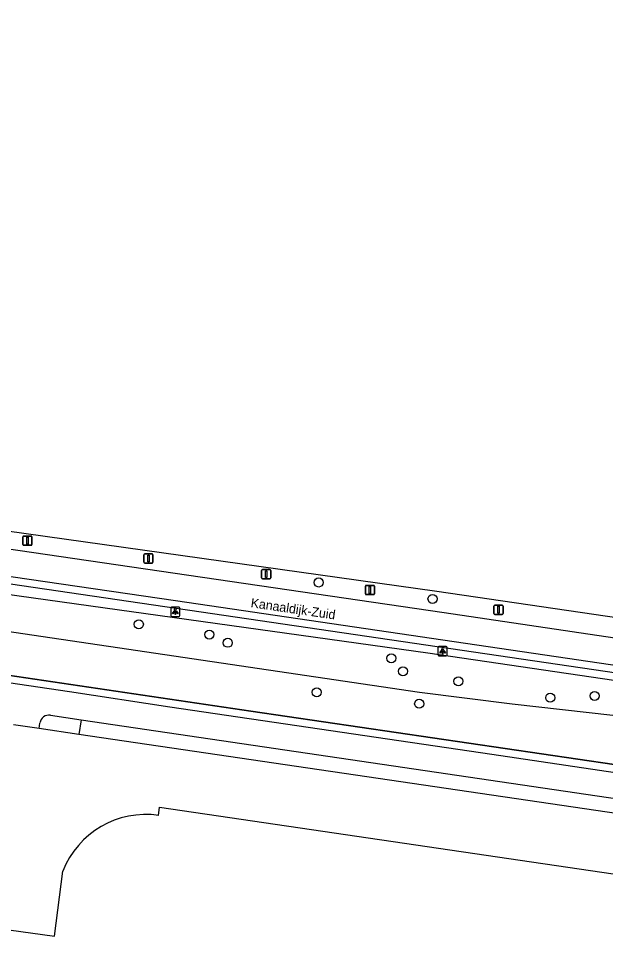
# Model space of a CAD drawing. Extents: x 163046 to 165074, y 382019 to 382874.
# Drawn here: x 163848.3 to 163911.6, y 382698.9 to 382799.6 of the extents above; entities that cross this region are included whole.
import ezdxf

# ---------------------------------------------------------------- set-up
doc = ezdxf.new("R2010")
doc.units = 0
for name, color, linetype in [('IMGEO_Afsluitpaal', 7, 'Continuous'), ('IMGEO_Boom', 7, 'Continuous'), ('IMGEO_Fietspad_gesloten', 7, 'Continuous'), ('IMGEO_Groenvoorziening', 7, 'Continuous'), ('IMGEO_Hek', 7, 'Continuous'), ('IMGEO_Lichtpunt', 7, 'Continuous'), ('IMGEO_Openbare_ruimte_label', 7, 'Continuous'), ('IMGEO_Rijbaan_lokaal_gesloten', 7, 'Continuous'), ('IMGEO_Rijbaan_lokaal_halfverhard', 7, 'Continuous'), ('IMGEO_Voetpad_open', 7, 'Continuous'), ('IMGEO_Waterloop', 7, 'Continuous')]:
    doc.layers.add(name, color=color, linetype=linetype)

msp = doc.modelspace()

# ---------------------------------------------------------------- linework, layer by layer
at = {"layer": 'IMGEO_Afsluitpaal'}
for p, q in [((163848.73, 382742.84), (163848.73, 382743.64)), ((163848.73, 382743.64), (163848.73, 382742.84)), ((163848.83, 382743.74), (163849.61, 382743.74)), ((163849.61, 382743.74), (163848.83, 382743.74)), ((163849.71, 382743.64), (163849.71, 382742.84)), ((163849.71, 382742.84), (163849.71, 382743.64)), ((163849.61, 382742.74), (163848.83, 382742.74)), ((163848.83, 382742.74), (163849.61, 382742.74)), ((163861.9, 382741.82), (163862.68, 382741.82)), ((163862.68, 382741.82), (163861.9, 382741.82)), ((163861.8, 382740.92), (163861.8, 382741.72)), ((163861.8, 382741.72), (163861.8, 382740.92)), ((163862.68, 382740.82), (163861.9, 382740.82)), ((163861.9, 382740.82), (163862.68, 382740.82)), ((163862.78, 382741.72), (163862.78, 382740.92)), ((163862.78, 382740.92), (163862.78, 382741.72)), ((163874.5, 382739.22), (163874.5, 382740.02)), ((163874.5, 382740.02), (163874.5, 382739.22)), ((163874.6, 382740.12), (163875.39, 382740.12)), ((163875.39, 382740.12), (163874.6, 382740.12)), ((163875.49, 382740.02), (163875.49, 382739.22)), ((163875.49, 382739.22), (163875.49, 382740.02)), ((163875.39, 382739.12), (163874.6, 382739.12)), ((163874.6, 382739.12), (163875.39, 382739.12)), ((163885.72, 382737.52), (163885.72, 382738.32)), ((163885.72, 382738.32), (163885.72, 382737.52)), ((163885.82, 382738.42), (163886.61, 382738.42)), ((163886.61, 382738.42), (163885.82, 382738.42)), ((163886.71, 382738.32), (163886.71, 382737.52)), ((163886.71, 382737.52), (163886.71, 382738.32)), ((163886.61, 382737.42), (163885.82, 382737.42)), ((163885.82, 382737.42), (163886.61, 382737.42)), ((163899.6, 382735.38), (163899.6, 382736.18)), ((163899.6, 382736.18), (163899.6, 382735.38)), ((163899.7, 382736.28), (163900.49, 382736.28)), ((163900.49, 382736.28), (163899.7, 382736.28)), ((163900.59, 382736.18), (163900.59, 382735.38)), ((163900.59, 382735.38), (163900.59, 382736.18)), ((163900.49, 382735.28), (163899.7, 382735.28)), ((163899.7, 382735.28), (163900.49, 382735.28))]:
    msp.add_line(p, q, dxfattribs=at)
for points in [[(163849.14, 382743.61), (163849.3, 382743.61), (163849.3, 382742.86), (163849.14, 382742.86), (163849.14, 382743.61)], [(163862.21, 382741.69), (163862.37, 382741.69), (163862.37, 382740.94), (163862.21, 382740.94), (163862.21, 382741.69)], [(163874.92, 382740), (163875.07, 382740), (163875.07, 382739.25), (163874.92, 382739.25), (163874.92, 382740)], [(163886.14, 382738.3), (163886.29, 382738.3), (163886.29, 382737.55), (163886.14, 382737.55), (163886.14, 382738.3)], [(163900.02, 382736.16), (163900.17, 382736.16), (163900.17, 382735.41), (163900.02, 382735.41), (163900.02, 382736.16)]]:
    msp.add_lwpolyline(points, dxfattribs=at)
for centre, start, end in [((163848.83, 382743.64), 90, 180), ((163848.83, 382743.64), 90, 180), ((163848.83, 382742.84), 180, 270), ((163848.83, 382742.84), 180, 270), ((163849.61, 382743.64), 0, 90), ((163849.61, 382743.64), 360, 90), ((163849.61, 382742.84), 270, 0), ((163849.61, 382742.84), 270, 0), ((163861.9, 382741.72), 90, 180), ((163861.9, 382741.72), 90, 180), ((163862.68, 382741.72), 0, 90), ((163862.68, 382741.72), 360, 90), ((163861.9, 382740.92), 180, 270), ((163861.9, 382740.92), 180, 270), ((163862.68, 382740.92), 270, 0), ((163862.68, 382740.92), 270, 0), ((163874.6, 382740.02), 90, 180), ((163874.6, 382740.02), 90, 180), ((163875.39, 382740.02), 0, 90), ((163875.39, 382740.02), 360, 90), ((163874.6, 382739.22), 180, 270), ((163874.6, 382739.22), 180, 270), ((163875.39, 382739.22), 270, 0), ((163875.39, 382739.22), 270, 0), ((163885.82, 382738.32), 90, 180), ((163885.82, 382738.32), 90, 180), ((163886.61, 382738.32), 0, 90), ((163886.61, 382738.32), 360, 90), ((163885.82, 382737.52), 180, 270), ((163885.82, 382737.52), 180, 270), ((163886.61, 382737.52), 270, 0), ((163886.61, 382737.52), 270, 0), ((163899.7, 382736.18), 90, 180), ((163899.7, 382736.18), 90, 180), ((163900.49, 382736.18), 0, 90), ((163900.49, 382736.18), 360, 90), ((163899.7, 382735.38), 180, 270), ((163899.7, 382735.38), 180, 270), ((163900.49, 382735.38), 270, 0), ((163900.49, 382735.38), 270, 0)]:
    msp.add_arc(centre, 0.1, start, end, dxfattribs=at)
at = {"layer": 'IMGEO_Boom'}
for centre in [(163880.68, 382738.73), (163892.97, 382736.96), (163861.25, 382734.22), (163868.87, 382733.11), (163870.86, 382732.22), (163888.52, 382730.55), (163889.78, 382729.15), (163895.77, 382728.07), (163880.47, 382726.88), (163905.68, 382726.29), (163910.47, 382726.49), (163891.53, 382725.64)]:
    msp.add_circle(centre, 0.489, dxfattribs=at)
at = {"layer": 'IMGEO_Fietspad_gesloten'}
for points in [[(163262.2, 382833.43), (163314.79, 382823.48), (163323.12, 382821.97), (163364.34, 382814.88), (163364.32, 382814.73), (163391.13, 382810.02), (163404.12, 382807.82), (163422.79, 382804.65), (163452.38, 382800.08), (163452.39, 382800.23), (163481.75, 382795.75), (163600.16, 382778.49), (163659.31, 382769.79), (163694.75, 382764.5), (163718.27, 382760.99), (163718.28, 382761.09), (163777.46, 382752.55), (163894.24, 382735.48), (163935.71, 382729.35)], [(164290.62, 382661.73), (164274.25, 382664.12), (164260.42, 382666.24), (164243.89, 382668.69), (164144.23, 382683.65), (164123, 382686.71), (164101.01, 382689.99), (164076.37, 382693.78), (164055.27, 382696.95), (164027.35, 382701.08), (164001.81, 382704.9), (163972.99, 382709.21), (163941.3, 382713.95), (163899.36, 382720.17), (163864.59, 382725.29), (163853.75, 382726.93), (163828.34, 382730.66), (163782.57, 382737.3), (163742.98, 382743.16), (163672.74, 382753.5), (163608.81, 382762.9), (163587.4, 382766.11), (163537.53, 382773.31), (163534.17, 382773.83)], [(163851.71, 382724.41), (163855.01, 382723.92)], [(163855.01, 382723.92), (164007.06, 382701.55)], [(163850.49, 382722.97), (163850.57, 382723.56)]]:
    msp.add_lwpolyline(points, dxfattribs=at)
msp.add_arc((163851.56, 382723.42), 1, 81.6669, 171.603, dxfattribs=at)
at = {"layer": 'IMGEO_Groenvoorziening'}
msp.add_lwpolyline([(163359.37, 382797.83), (163374.85, 382798.03), (163401.89, 382794.15), (163410.94, 382792.85), (163500, 382779.47), (163535.41, 382774.6), (163550.62, 382772.33), (163693.06, 382751.36), (163828.8, 382731.36), (163846.1, 382728.88), (163873.33, 382724.84), (163916.5, 382718.52), (163943.51, 382714.37), (163981.6, 382708.67), (164080.42, 382694.02), (164103.91, 382690.52), (164197.42, 382676.27), (164217.65, 382673.07), (164282.56, 382663.33), (164518.36, 382627.93)], dxfattribs=at)
at = {"layer": 'IMGEO_Hek'}
msp.add_lwpolyline([(163981.6, 382708.67), (163943.51, 382714.37), (163916.5, 382718.52), (163873.33, 382724.84), (163846.1, 382728.88), (163828.8, 382731.36), (163693.06, 382751.36)], dxfattribs=at)
at = {"layer": 'IMGEO_Lichtpunt'}
for p, q in [((163864.69, 382735.97), (163864.69, 382735.16)), ((163864.69, 382735.97), (163864.69, 382735.16)), ((163865.59, 382736.07), (163864.79, 382736.07)), ((163865.59, 382736.07), (163864.79, 382736.07)), ((163865.69, 382735.16), (163865.69, 382735.97)), ((163865.69, 382735.16), (163865.69, 382735.97)), ((163864.79, 382735.07), (163865.59, 382735.07)), ((163864.79, 382735.07), (163865.59, 382735.07)), ((163894.46, 382731.81), (163893.66, 382731.81)), ((163894.46, 382731.81), (163893.66, 382731.81)), ((163893.56, 382731.72), (163893.56, 382730.91)), ((163893.56, 382731.72), (163893.56, 382730.91)), ((163893.66, 382730.81), (163894.46, 382730.81)), ((163893.66, 382730.81), (163894.46, 382730.81)), ((163894.56, 382730.91), (163894.56, 382731.72)), ((163894.56, 382730.91), (163894.56, 382731.72))]:
    msp.add_line(p, q, dxfattribs=at)
for points in [[(163865.07, 382735.63), (163865.11, 382735.61), (163864.92, 382735.34), (163864.88, 382735.37), (163865.07, 382735.63)], [(163865.17, 382735.59), (163865.22, 382735.59), (163865.22, 382735.26), (163865.17, 382735.26), (163865.17, 382735.59)], [(163865.28, 382735.61), (163865.32, 382735.63), (163865.5, 382735.37), (163865.47, 382735.34), (163865.28, 382735.61)], [(163893.94, 382731.38), (163893.97, 382731.35), (163893.79, 382731.09), (163893.75, 382731.12), (163893.94, 382731.38)], [(163894.04, 382731.33), (163894.09, 382731.33), (163894.09, 382731.01), (163894.04, 382731.01), (163894.04, 382731.33)], [(163894.15, 382731.35), (163894.19, 382731.38), (163894.37, 382731.12), (163894.33, 382731.09), (163894.15, 382731.35)]]:
    msp.add_lwpolyline(points, dxfattribs=at)
for centre in [(163865.19, 382735.77), (163894.06, 382731.51)]:
    msp.add_circle(centre, 0.0994, dxfattribs=at)
for centre, start, end in [((163864.79, 382735.97), 90, 180), ((163864.79, 382735.97), 90, 180), ((163865.59, 382735.97), 0, 90), ((163865.59, 382735.97), 0, 90), ((163864.79, 382735.16), 180, 270), ((163864.79, 382735.16), 180, 270), ((163865.59, 382735.16), 270, 0), ((163865.59, 382735.16), 270, 360), ((163893.66, 382731.72), 90, 180), ((163893.66, 382731.72), 90, 180), ((163894.46, 382731.72), 0, 90), ((163894.46, 382731.72), 0, 90), ((163893.66, 382730.91), 180, 270), ((163893.66, 382730.91), 180, 270), ((163894.46, 382730.91), 270, 0), ((163894.46, 382730.91), 270, 360)]:
    msp.add_arc(centre, 0.0946, start, end, dxfattribs=at)
at = {"layer": 'IMGEO_Rijbaan_lokaal_gesloten'}
for points in [[(163850.49, 382722.97), (163847.72, 382723.38)], [(163854.78, 382722.34), (163850.49, 382722.97)], [(164006.84, 382699.97), (164000, 382700.98), (163854.78, 382722.34)], [(163863.39, 382713.59), (163863.49, 382714.49), (163994.3, 382695.27)], [(163838.61, 382702.43), (163852.13, 382700.57), (163853.05, 382707.56)]]:
    msp.add_lwpolyline(points, dxfattribs=at)
msp.add_arc((163862.01, 382704.07), 9.62, 81.7292, 158.6852, dxfattribs=at)
at = {"layer": 'IMGEO_Rijbaan_lokaal_halfverhard'}
for points in [[(163935.2, 382726.45), (163865.22, 382736.76), (163777.02, 382749.58), (163717.86, 382758.17), (163694.37, 382761.68), (163658.89, 382766.97), (163481.33, 382792.88), (163422.35, 382801.94), (163403.68, 382805.1), (163390.65, 382807.22), (163363.84, 382811.92), (163322.62, 382819.12), (163314.27, 382820.6), (163290.92, 382824.68), (163261.84, 382830.05)], [(163322.47, 382818.43), (163367.47, 382810.55), (163392.06, 382806.33), (163416.38, 382802.09), (163437.86, 382798.77), (163477.86, 382792.74), (163535.08, 382784.39), (163586.49, 382776.8), (163665.19, 382765.27), (163724.04, 382756.55), (163797.09, 382745.94), (163942.52, 382724.63), (163982.95, 382718.82), (164038.68, 382710.5), (164106.21, 382700.45), (164167.93, 382691.09), (164227.93, 382681.9), (164243.96, 382679.59)]]:
    msp.add_lwpolyline(points, dxfattribs=at)
at = {"layer": 'IMGEO_Voetpad_open'}
msp.add_lwpolyline([(163855.01, 382723.92), (163854.78, 382722.34)], dxfattribs=at)
at = {"layer": 'IMGEO_Waterloop'}
for points in [[(163181.62, 382853.49), (163197.03, 382850.28), (163305.26, 382829.6), (163305.57, 382830.01), (163310.04, 382829.2), (163310.24, 382828.46), (163351.91, 382819.96), (163378.29, 382814.85), (163404.52, 382810.31), (163423.67, 382806.99), (163441.72, 382804), (163484.72, 382798.05), (163500, 382795.74), (163550.36, 382788.13), (163695.04, 382766.67), (163750, 382758.53), (163787.83, 382753.17), (163808.82, 382750), (163842.64, 382744.9), (163893.44, 382737.78), (163957.08, 382728.48), (163984.26, 382724.67)], [(163960.72, 382718.96), (163901.57, 382725.6), (163891.58, 382726.84), (163814.14, 382738.31), (163792.78, 382741.61), (163745.19, 382750), (163693.63, 382755.7), (163644.4, 382763.31), (163599.03, 382769.82), (163550.48, 382777.74), (163531.31, 382780.73), (163500, 382785.31), (163403.56, 382799.39), (163402.77, 382799.54), (163335.61, 382812.21), (163322.88, 382814.5)], [(163337.61, 382814.84), (163359.3, 382810.82), (163403.34, 382803.03), (163422.96, 382799.57), (163500, 382787.56), (163548.66, 382779.98), (163558.31, 382778.65), (163599.59, 382773.47), (163692, 382760.32), (163694.14, 382759.99), (163759.96, 382750), (163780.57, 382747.06), (163793.38, 382745.36), (163843.66, 382737.95), (163892.47, 382731.14), (163941.47, 382723.93), (163961.29, 382721.23)]]:
    msp.add_lwpolyline(points, dxfattribs=at)

# ---------------------------------------------------------------- texts
at = {"layer": 'IMGEO_Openbare_ruimte_label'}
msp.add_text('Kanaaldijk-Zuid', height=1, rotation=351.6591, dxfattribs=at).set_placement((163873.29, 382736.07))

doc.saveas('drawing.dxf')
